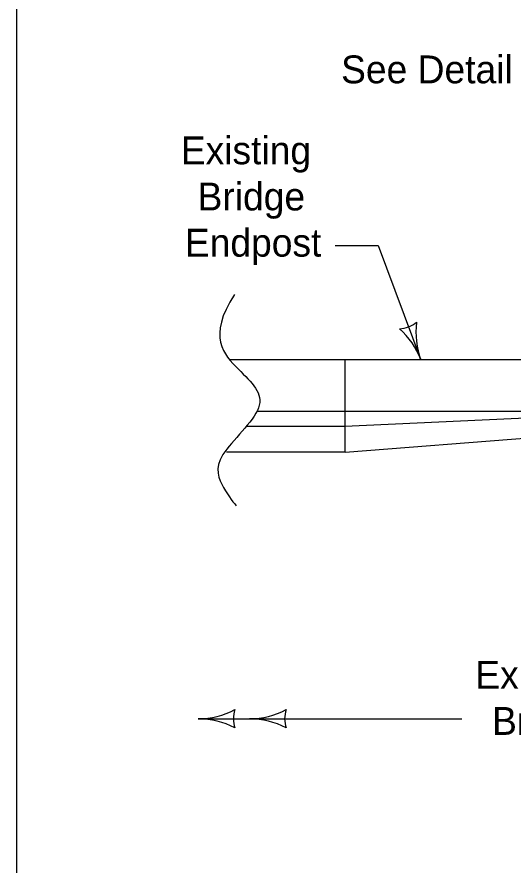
# Model space of a CAD drawing. Extents: x 10028 to 81668, y 3581 to 11018.
# Drawn here: x 17332.5 to 17603.6, y 8498.9 to 8961.7 of the extents above; entities that cross this region are included whole.
import ezdxf

# ---------------------------------------------------------------- set-up
doc = ezdxf.new("R2010")
doc.units = 0
for name, color, linetype in [('dsnCellsNorthArrow', 7, 'Continuous'), ('dsnTextTabulation', 7, 'Continuous'), ('Level 9', 7, 'Continuous'), ('SheetBorder', 7, 'Continuous')]:
    doc.layers.add(name, color=color, linetype=linetype)

msp = doc.modelspace()

# ---------------------------------------------------------------- linework, layer by layer
at = {"layer": 'dsnTextTabulation'}
for p, q in [((17506.31, 8836.96), (17529.91, 8836.96)), ((17529.91, 8836.96), (17553.19, 8774.63)), ((17511.6, 8774.63), (17448.68, 8774.63)), ((17687.31, 8774.63), (17511.6, 8774.63)), ((17511.6, 8774.63), (17511.6, 8724.16)), ((17694.57, 8746.43), (17511.6, 8746.43)), ((17511.8, 8724.18), (17696.58, 8738.84)), ((17511.8, 8724.18), (17446.92, 8724.18)), ((17431.58, 8578.73), (17575.55, 8578.73))]:
    msp.add_line(p, q, dxfattribs=at)
for centre, radius, start, end in [((17540.72, 8808.01), 16.42, 272.7406, 308.2073), ((17593, 8789.49), 42.5, 172.4015, 200.4739), ((17513.37, 8759.76), 42.5, 20.4739, 48.5464), ((17431.58, 8621.23), 42.5, 270, 298.0725), ((17467.21, 8578.73), 16.42, 162.2666, 197.7334), ((17459.56, 8621.23), 42.5, 270, 298.0725), ((17495.2, 8578.73), 16.42, 162.2666, 197.7334), ((17431.58, 8536.23), 42.5, 61.9275, 90), ((17459.56, 8536.23), 42.5, 61.9275, 90)]:
    msp.add_arc(centre, radius, start, end, dxfattribs=at)
at = {"layer": 'Level 9'}
for p, q in [((17511.6, 8746.43), (17463.59, 8746.43)), ((17694.57, 8746.43), (17511.6, 8738.31)), ((17511.6, 8738.31), (17457.91, 8738.31))]:
    msp.add_line(p, q, dxfattribs=at)
msp.add_open_spline([(17451.34, 8810.2), (17436.25, 8787.12), (17454.89, 8767.59), (17473.52, 8750.72), (17438.02, 8720.53), (17444.89, 8704.3), (17451.59, 8695.77), (17452.26, 8694.93)], degree=3, dxfattribs=at)
at = {"layer": 'SheetBorder'}
msp.add_lwpolyline([(17332.52, 9944.02), (20467.53, 9944.02), (20467.53, 7924.02), (17332.52, 7924.02)], close=True, dxfattribs=at)

# ---------------------------------------------------------------- texts
at = {"layer": 'dsnCellsNorthArrow'}
for s, p in [("See Detail 'A'", (17509.6, 8925.51)), ('Existing', (17422.04, 8881.33)), ('Bridge', (17431.2, 8856.13)), ('Endpost', (17424.26, 8830.93)), ('Existing', (17582.93, 8595.13)), ('Bridge', (17592.09, 8569.93))]:
    msp.add_text(s, height=15.2, dxfattribs=at).set_placement(p)

doc.saveas('drawing.dxf')
